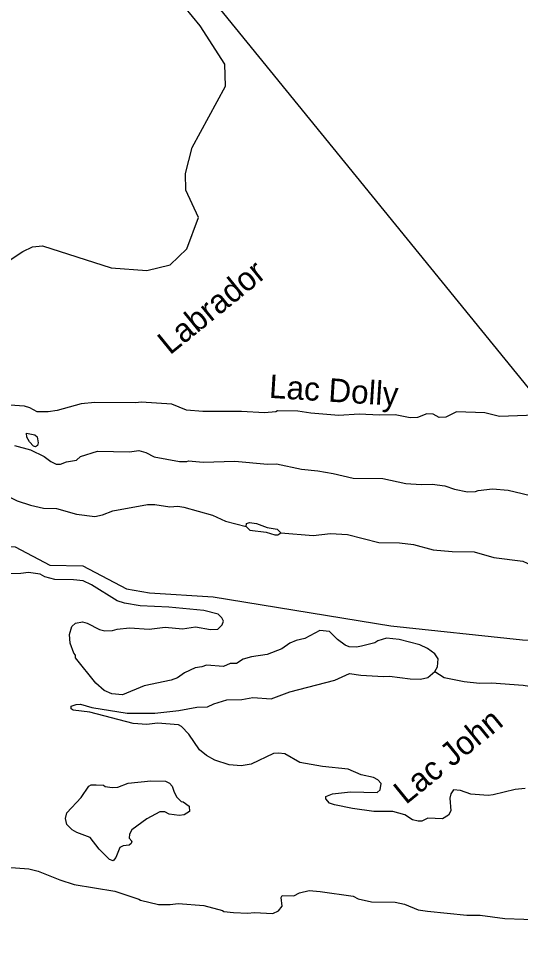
# Model space of a CAD drawing. Extents: x 347059 to 352153, y 6073752 to 6078601.
# Drawn here: x 351006.5 to 351123.8, y 6077359.2 to 6077579.9 of the extents above; entities that cross this region are included whole.
import ezdxf

# ---------------------------------------------------------------- set-up
doc = ezdxf.new("R2010")
doc.units = 0
doc.layers.add('Level 63', color=7, linetype='Continuous')

msp = doc.modelspace()

# ---------------------------------------------------------------- linework, layer by layer
at = {"layer": 'Level 63'}
msp.add_lwpolyline([(350822.11, 6077057.72), (351218.14, 6077379.8), (350976.59, 6077676.83), (350580.55, 6077354.75)], close=True, dxfattribs=at)
for points in [[(351002.31, 6077522.06), (351007.37, 6077525.43), (351009.64, 6077526.46), (351012.03, 6077526.71), (351028.03, 6077521.53), (351036.41, 6077520.94), (351041.85, 6077522.26), (351045.78, 6077526.05), (351048.51, 6077533.35), (351045.54, 6077539.77), (351045.48, 6077543.68), (351047.01, 6077549.72), (351054.8, 6077564.12), (351054.67, 6077569.28), (351048.92, 6077578.22), (351045.28, 6077582.59)], [(351127.37, 6077487.09), (351118.96, 6077486.78), (351115.51, 6077487.57), (351108.91, 6077487.85), (351106.39, 6077486.62), (351104.78, 6077486.5), (351103.38, 6077487.27), (351101.94, 6077487.35), (351099.74, 6077486.54), (351098.05, 6077486.43), (351094.5, 6077487.15), (351090.85, 6077487.05), (351086.06, 6077487.29), (351081.34, 6077487.01), (351074.81, 6077487.51), (351071.77, 6077487.98), (351067.01, 6077488.07), (351066.62, 6077487.85), (351063.91, 6077487.59), (351058.54, 6077487.95), (351049.49, 6077487.94), (351045.7, 6077488.23), (351042.28, 6077489.61), (351035.11, 6077490.09), (351033.87, 6077489.93), (351024.28, 6077489.99), (351021.02, 6077489.71), (351015.41, 6077488.18), (351013.33, 6077487.85), (351010.74, 6077487.86), (351009.03, 6077488.8), (351007.8, 6077489.13), (351004.38, 6077489.38)], [(351008.25, 6077482.85), (351010.19, 6077482.42), (351010.73, 6077481.95), (351010.97, 6077480.6), (351010.84, 6077479.93), (351010.4, 6077479.67), (351009.91, 6077479.77), (351008.95, 6077480.8), (351008.35, 6077481.88), (351008.25, 6077482.85)], [(351005.43, 6077479.92), (351009.21, 6077478.91), (351012.43, 6077477.37), (351013.97, 6077476.22), (351015.17, 6077475.62), (351016.21, 6077475.62), (351017.6, 6077476.13), (351019.96, 6077476.52), (351020.93, 6077477.35), (351024.9, 6077478.59), (351032.35, 6077478.48), (351034.56, 6077478.75), (351036.19, 6077478.32), (351038.11, 6077477.3), (351044.07, 6077476.2), (351045.79, 6077476.17), (351046.13, 6077476.35), (351049.6, 6077476.05), (351057.04, 6077476.26), (351064.68, 6077475.58), (351066.74, 6077475.65), (351072.63, 6077474.41), (351076.4, 6077474.03), (351080.05, 6077473.39), (351084.69, 6077472.32), (351091.64, 6077472.22), (351097.04, 6077471.09), (351100.6, 6077470.79), (351103.2, 6077470.87), (351106.16, 6077470.5), (351108.38, 6077469.73), (351111.44, 6077469.12), (351113.35, 6077469.15), (351113.97, 6077469.39), (351117.3, 6077469.8), (351120.99, 6077469.52), (351127.84, 6077467.89)], [(350946.7, 6077472.06), (350949.26, 6077472.92), (350953.29, 6077473.15), (350960.23, 6077473.05), (350962.66, 6077472.43), (350979.01, 6077460.98), (350993.74, 6077456.92), (351005.61, 6077456.21), (351013.71, 6077451.93), (351021.43, 6077451.78), (351031.67, 6077446.41), (351037.01, 6077445.48), (351051.94, 6077444.48), (351093.48, 6077437.75), (351124.35, 6077434.45), (351131.34, 6077434.31), (351142.03, 6077435.11), (351154.52, 6077436.83), (351166.28, 6077436.27), (351173.82, 6077434.3)], [(350997.98, 6077464.35), (350998.21, 6077464.68), (350998.45, 6077466.97), (350999.12, 6077467.98), (351001.33, 6077468.57), (351003.26, 6077468.37), (351006.04, 6077466.98), (351009.19, 6077465.95), (351012.24, 6077465.25), (351015.28, 6077465.19), (351019.93, 6077463.88), (351024.27, 6077463.3), (351026.05, 6077463.71), (351028.45, 6077464.69), (351036.59, 6077466.17), (351038.31, 6077466.14), (351041.83, 6077465.56), (351043.63, 6077465.75), (351045.1, 6077465.52), (351051.77, 6077463.6), (351054.84, 6077462.26), (351059.63, 6077460.98)], [(351059.63, 6077460.98), (351059.76, 6077461.65), (351060.47, 6077461.88), (351062.08, 6077461.67), (351064.6, 6077460.72), (351066.88, 6077460.39), (351067.73, 6077459.52)], [(351059.63, 6077460.98), (351060.53, 6077460.14), (351064.33, 6077459.62), (351066.39, 6077459.05), (351067.07, 6077459.01), (351067.73, 6077459.52)], [(351067.73, 6077459.52), (351075.33, 6077458.89), (351079.4, 6077459.38), (351083.36, 6077459.07), (351090.72, 6077457.2), (351095.53, 6077457.14), (351098.84, 6077456.73), (351103.42, 6077455.52), (351107.83, 6077455.15), (351113.01, 6077455.05), (351117.61, 6077453.71), (351124.42, 6077452.86), (351126.44, 6077451.92), (351128.51, 6077451.76), (351129.85, 6077453.04), (351134.43, 6077453.29)], [(351053.04, 6077436.93), (351054.08, 6077437.98), (351054.32, 6077438.82), (351053.96, 6077439.59), (351053.07, 6077440.43), (351049.72, 6077441.3), (351041.59, 6077442.09), (351034.86, 6077442.42), (351031.16, 6077443.02), (351029.45, 6077443.55), (351023.46, 6077447.3), (351021.49, 6077448.27), (351019.29, 6077448.5), (351014.88, 6077448.55), (351012.55, 6077449.16), (351011.45, 6077449.84), (351008.73, 6077450.23), (351006.92, 6077449.95), (351004.55, 6077449.89)], [(351090.49, 6077434.22), (351089.8, 6077433.76), (351086.65, 6077432.92), (351085.44, 6077432.71), (351083.72, 6077432.83), (351082.86, 6077433.21), (351081.03, 6077434.53), (351079.12, 6077436.36), (351076.92, 6077436.59), (351073.41, 6077434.75), (351071.36, 6077434.28), (351069.91, 6077433.64), (351068.02, 6077432.33), (351064.58, 6077431.03), (351060.88, 6077430.49), (351058.99, 6077429.91), (351057.41, 6077428.93), (351055.9, 6077428.89), (351054.32, 6077428.22), (351050.36, 6077428.53), (351049.31, 6077428.12), (351047.73, 6077427.86), (351045.26, 6077426.67), (351043.57, 6077425.51), (351042.1, 6077425.01), (351035.79, 6077423.66), (351030.71, 6077421.57), (351028.19, 6077421.79), (351026.43, 6077422.6), (351024.46, 6077424.3), (351019.74, 6077430.26), (351019.72, 6077430.81), (351019.33, 6077431.31), (351018.44, 6077433.69), (351018.33, 6077435.71), (351018.83, 6077437.56), (351019.75, 6077438.35), (351021.38, 6077438.65), (351022.48, 6077438.37), (351025.34, 6077436.88), (351026.62, 6077436.58), (351028.4, 6077436.59), (351029.49, 6077436.95), (351032.39, 6077437.27), (351036.95, 6077436.93), (351040.73, 6077437.37), (351044.78, 6077437.05), (351047.84, 6077437.49), (351051.35, 6077436.82), (351053.04, 6077436.93)], [(351077.5, 6077404.78), (351072.25, 6077405.7), (351068.68, 6077407.7), (351067.24, 6077407.87), (351066.06, 6077407.84), (351060.83, 6077405.31), (351058.51, 6077404.96), (351055.68, 6077405.18), (351052.31, 6077406.28), (351050.4, 6077407.38), (351048.75, 6077408.68), (351046.24, 6077412.31), (351044.51, 6077414.12), (351043.79, 6077414.53), (351038.93, 6077414.95), (351036.39, 6077414.59), (351033.19, 6077414.85), (351023.11, 6077417.51), (351019.21, 6077417.96), (351018.71, 6077418.29), (351018.73, 6077418.88), (351019.84, 6077419.33), (351020.88, 6077419.34), (351023.51, 6077418.56), (351031.81, 6077417.25), (351038.32, 6077417.3), (351043.94, 6077417.87), (351048.12, 6077418.63), (351050.6, 6077418.77), (351052.09, 6077419.45), (351055.11, 6077420.35), (351058.67, 6077420.45), (351061.19, 6077420.95), (351065.47, 6077420.65), (351069.86, 6077422.28), (351080.38, 6077424.97), (351083.85, 6077426.54), (351086.49, 6077426.17), (351091.76, 6077425.83), (351093.23, 6077425.92), (351098.02, 6077425.27), (351100.47, 6077425.24), (351102.15, 6077425.58), (351103.78, 6077427.01), (351104.46, 6077428.11), (351104.61, 6077430), (351103.8, 6077431.15), (351102.09, 6077432.41), (351100.29, 6077433.27), (351095.49, 6077434.55), (351092.47, 6077434.79), (351090.49, 6077434.22)], [(351103.78, 6077427.01), (351105.97, 6077425.65), (351110.68, 6077424.7), (351114.22, 6077424.3), (351117.05, 6077424.4), (351124.48, 6077423.79), (351128.94, 6077423.15)], [(351124.92, 6077399.64), (351122.62, 6077399.38), (351117.46, 6077398.11), (351116.26, 6077397.99), (351112.25, 6077398.26), (351109.81, 6077399.11), (351108.19, 6077399.31), (351107.53, 6077398.4), (351107.31, 6077397.33), (351107.58, 6077394.39), (351107, 6077393.37), (351105.57, 6077392.5), (351102.13, 6077392.66), (351100.73, 6077391.97), (351099.91, 6077391.98), (351098.54, 6077392.29), (351096.82, 6077393.46), (351093.96, 6077394.22), (351089.51, 6077394.23), (351084.54, 6077394.9), (351080.29, 6077395.79), (351079.16, 6077396.2), (351078.28, 6077397.22), (351078.26, 6077397.77), (351079.89, 6077398.39), (351084.04, 6077398.87), (351090.33, 6077398.68), (351091.05, 6077399.31), (351091.23, 6077400.75), (351090.43, 6077401.66), (351089.45, 6077402.2), (351086.53, 6077402.83), (351083.56, 6077404.16), (351077.5, 6077404.78)], [(351022.81, 6077400.14), (351023.35, 6077400.48), (351024.54, 6077400.51), (351026.25, 6077400.39), (351026.63, 6077400.12), (351028.28, 6077399.86), (351029.6, 6077399.93), (351032.04, 6077400.85), (351037.34, 6077401.42), (351040.78, 6077401.35), (351041.73, 6077400.87), (351042.36, 6077400.15), (351042.78, 6077398.78), (351043.46, 6077397.61), (351044.42, 6077396.58), (351044.91, 6077396.47), (351046.33, 6077395.48), (351046.4, 6077394.24), (351045.16, 6077393.44), (351044.01, 6077393.26), (351041.64, 6077393.61), (351040.66, 6077394.14), (351039.43, 6077394.15), (351036.41, 6077392.53), (351032.91, 6077389.96), (351032.33, 6077388.95), (351032.29, 6077387.95), (351032.89, 6077387.28), (351032.78, 6077386.71), (351032.27, 6077386.32), (351030.84, 6077386.18), (351030.11, 6077385.77), (351029.18, 6077383.43), (351028.55, 6077382.69), (351027.67, 6077382.98), (351025.24, 6077385.37), (351023.18, 6077388.13), (351020, 6077389.3), (351018.94, 6077389.93), (351017.7, 6077391.22), (351017.42, 6077392.62), (351017.71, 6077393.91), (351021.03, 6077397.54), (351022.81, 6077400.14)], [(350998.3, 6077381.55), (351008.81, 6077380.83), (351011.01, 6077380.28), (351016.08, 6077378.24), (351019.44, 6077377.14), (351028.89, 6077375.6), (351034.56, 6077373.71), (351034.94, 6077373.43), (351039.18, 6077372.45), (351041.86, 6077372.43), (351043.76, 6077372.7), (351049.79, 6077372.22), (351054.15, 6077371.08), (351054.44, 6077370.82), (351056.68, 6077370.54), (351060.03, 6077370.4), (351061.5, 6077370.58), (351065.89, 6077370.35), (351067.24, 6077371), (351068.1, 6077372.07), (351067.81, 6077374.11), (351068.09, 6077374.57), (351070.81, 6077374.51), (351072.17, 6077375.16), (351074.42, 6077375.7), (351076.99, 6077375.51), (351084.72, 6077374.41), (351085.86, 6077373.77), (351088.97, 6077373.11), (351094.5, 6077372.97), (351096.71, 6077372.51)], [(351096.71, 6077372.51), (351099.91, 6077371.2), (351102.1, 6077370.88), (351111.26, 6077369.92), (351114.4, 6077369.94), (351120.17, 6077369.17), (351129.09, 6077368.83)]]:
    msp.add_lwpolyline(points, dxfattribs=at)

# ---------------------------------------------------------------- texts
for s, rotation, p in [('Labrador', 39.1198, (351041.81, 6077501.02)), ('Lac Dolly', 356.351, (351064.9, 6077491.13)), ('Lac John', 39.1198, (351097.02, 6077395.71))]:
    msp.add_text(s, height=5.5, rotation=rotation, dxfattribs=at).set_placement(p)

doc.saveas('drawing.dxf')
